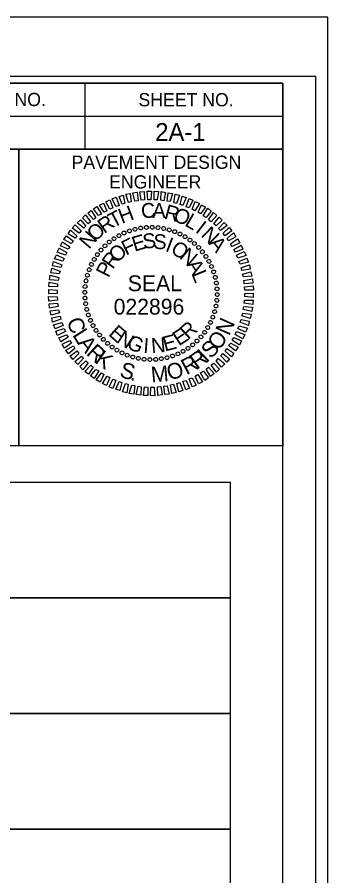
# Model space of a CAD drawing. Extents: x 573732 to 574187, y -53389 to -53257.
# Drawn here: x 573970.18 to 573984.3, y -53296.01 to -53256.95 of the extents above; entities that cross this region are included whole.
import ezdxf

# ---------------------------------------------------------------- set-up
doc = ezdxf.new("R2010")
doc.units = 0
for name, color, linetype in [('Old_Level_19', 7, 'Continuous'), ('Sheet Cutting Line CELL', 7, 'Continuous'), ('Sheet Data Field CELL', 7, 'Continuous'), ('Sheet PE Seal CELL', 7, 'Continuous'), ('Sheet Plot Border Inside CELL', 7, 'Continuous'), ('Sheet Plot Border Outside CELL', 7, 'Continuous'), ('Sheet Typical CELL', 7, 'Continuous')]:
    doc.layers.add(name, color=color, linetype=linetype)

msp = doc.modelspace()

# ---------------------------------------------------------------- linework, layer by layer
at = {"layer": 'Old_Level_19'}
msp.add_lwpolyline([(573928.412, -53278.106), (573979.868, -53278.106), (573979.868, -53283.369), (573928.412, -53283.369)], close=True, dxfattribs=at)
for points in [[(573933.675, -53288.632), (573928.412, -53288.632), (573928.412, -53283.369), (573979.867, -53283.369), (573979.867, -53288.632), (573933.675, -53288.632), (573933.675, -53283.369)], [(573933.675, -53293.895), (573928.412, -53293.895), (573928.412, -53288.631), (573979.867, -53288.631), (573979.867, -53293.895), (573933.675, -53293.895), (573933.675, -53288.631)], [(573933.675, -53299.156), (573928.412, -53299.156), (573928.412, -53293.893), (573979.867, -53293.893), (573979.867, -53299.156), (573933.675, -53299.156), (573933.675, -53293.893)]]:
    msp.add_lwpolyline(points, dxfattribs=at)
at = {"layer": 'Sheet Cutting Line CELL'}
msp.add_line((573984.302, -53256.948), (573782.222, -53256.948), dxfattribs=at)
at = {"layer": 'Sheet PE Seal CELL'}
for p, q in [((573975.04, -53266.763), (573975.04, -53266.763)), ((573975.28, -53266.667), (573975.28, -53266.667)), ((573975.532, -53266.595), (573975.532, -53266.595)), ((573975.796, -53266.547), (573975.796, -53266.547)), ((573976.054, -53266.511), (573976.054, -53266.511)), ((573976.318, -53266.505), (573976.318, -53266.505)), ((573976.582, -53266.523), (573976.582, -53266.523)), ((573976.84, -53266.565), (573976.84, -53266.565)), ((573977.092, -53266.619), (573977.092, -53266.619)), ((573977.344, -53266.703), (573977.344, -53266.703)), ((573977.584, -53266.811), (573977.584, -53266.811)), ((573974.368, -53267.171), (573974.368, -53267.171)), ((573974.578, -53267.021), (573974.578, -53267.021)), ((573974.806, -53266.883), (573974.806, -53266.883)), ((573977.818, -53266.931), (573977.818, -53266.931)), ((573978.034, -53267.081), (573978.034, -53267.081)), ((573973.99, -53267.537), (573973.99, -53267.537)), ((573974.17, -53267.351), (573974.17, -53267.351)), ((573978.244, -53267.243), (573978.244, -53267.243)), ((573978.43, -53267.423), (573978.43, -53267.423)), ((573973.678, -53267.963), (573973.678, -53267.963)), ((573973.828, -53267.747), (573973.828, -53267.747)), ((573978.61, -53267.621), (573978.61, -53267.621)), ((573978.76, -53267.831), (573978.76, -53267.831)), ((573973.558, -53268.197), (573973.558, -53268.197)), ((573978.898, -53268.059), (573978.898, -53268.059)), ((573979.018, -53268.293), (573979.018, -53268.293)), ((573973.366, -53268.689), (573973.366, -53268.689)), ((573973.45, -53268.437), (573973.45, -53268.437)), ((573979.114, -53268.533), (573979.114, -53268.533)), ((573973.312, -53268.941), (573973.312, -53268.941)), ((573979.186, -53268.785), (573979.186, -53268.785)), ((573979.234, -53269.049), (573979.234, -53269.049)), ((573973.252, -53269.463), (573973.252, -53269.463)), ((573973.27, -53269.199), (573973.27, -53269.199)), ((573976.264, -53269.517), (573976.264, -53269.517)), ((573979.27, -53269.307), (573979.27, -53269.307)), ((573973.258, -53269.727), (573973.258, -53269.727)), ((573979.258, -53269.835), (573979.258, -53269.835)), ((573979.276, -53269.571), (573979.276, -53269.571)), ((573973.294, -53269.985), (573973.294, -53269.985)), ((573973.342, -53270.249), (573973.342, -53270.249)), ((573979.216, -53270.093), (573979.216, -53270.093)), ((573973.414, -53270.501), (573973.414, -53270.501)), ((573979.078, -53270.597), (573979.078, -53270.597)), ((573979.162, -53270.345), (573979.162, -53270.345)), ((573973.51, -53270.741), (573973.51, -53270.741)), ((573973.63, -53270.975), (573973.63, -53270.975)), ((573978.85, -53271.071), (573978.85, -53271.071)), ((573978.97, -53270.837), (573978.97, -53270.837)), ((573973.768, -53271.203), (573973.768, -53271.203)), ((573973.918, -53271.413), (573973.918, -53271.413)), ((573978.538, -53271.497), (573978.538, -53271.497)), ((573978.7, -53271.287), (573978.7, -53271.287)), ((573974.098, -53271.611), (573974.098, -53271.611)), ((573974.284, -53271.791), (573974.284, -53271.791)), ((573978.16, -53271.863), (573978.16, -53271.863)), ((573978.358, -53271.683), (573978.358, -53271.683)), ((573974.494, -53271.953), (573974.494, -53271.953)), ((573974.71, -53272.103), (573974.71, -53272.103)), ((573974.944, -53272.223), (573974.944, -53272.223)), ((573977.488, -53272.271), (573977.488, -53272.271)), ((573977.722, -53272.151), (573977.722, -53272.151)), ((573977.95, -53272.013), (573977.95, -53272.013)), ((573975.184, -53272.331), (573975.184, -53272.331)), ((573975.436, -53272.415), (573975.436, -53272.415)), ((573975.688, -53272.469), (573975.688, -53272.469)), ((573975.946, -53272.511), (573975.946, -53272.511)), ((573976.21, -53272.529), (573976.21, -53272.529)), ((573976.474, -53272.523), (573976.474, -53272.523)), ((573976.732, -53272.487), (573976.732, -53272.487)), ((573976.996, -53272.439), (573976.996, -53272.439)), ((573977.248, -53272.367), (573977.248, -53272.367))]:
    msp.add_line(p, q, dxfattribs=at)
for points in [[(573975.82, -53265.281), (573975.754, -53264.897), (573975.958, -53264.873), (573975.964, -53265.263)], [(573976.12, -53265.251), (573976.09, -53264.861), (573976.288, -53264.867), (573976.264, -53265.257)], [(573976.408, -53265.257), (573976.408, -53264.867), (573976.606, -53264.873), (573976.552, -53265.263)], [(573974.398, -53265.683), (573974.206, -53265.347), (573974.392, -53265.263), (573974.53, -53265.629)], [(573974.662, -53265.557), (573974.506, -53265.209), (573974.686, -53265.137), (573974.812, -53265.521)], [(573974.956, -53265.461), (573974.818, -53265.101), (573975.004, -53265.047), (573975.082, -53265.419)], [(573975.244, -53265.383), (573975.118, -53265.005), (573975.322, -53264.963), (573975.37, -53265.353)], [(573975.532, -53265.317), (573975.436, -53264.933), (573975.634, -53264.915), (573975.676, -53265.299)], [(573976.708, -53265.275), (573976.732, -53264.885), (573976.93, -53264.921), (573976.852, -53265.299)], [(573976.996, -53265.323), (573977.05, -53264.939), (573977.248, -53264.969), (573977.14, -53265.341)], [(573977.302, -53265.389), (573977.362, -53264.999), (573977.566, -53265.047), (573977.428, -53265.419)], [(573977.59, -53265.467), (573977.68, -53265.095), (573977.866, -53265.155), (573977.716, -53265.509)], [(573977.86, -53265.575), (573977.998, -53265.197), (573978.166, -53265.269), (573977.998, -53265.617)], [(573973.876, -53265.977), (573973.654, -53265.671), (573973.81, -53265.557), (573974.008, -53265.905)], [(573974.14, -53265.827), (573973.918, -53265.503), (573974.104, -53265.407), (573974.254, -53265.755)], [(573978.13, -53265.689), (573978.28, -53265.335), (573978.466, -53265.419), (573978.262, -53265.755)], [(573978.406, -53265.827), (573978.568, -53265.485), (573978.748, -53265.587), (573978.52, -53265.899)], [(573978.64, -53265.989), (573978.85, -53265.641), (573979.006, -53265.767), (573978.772, -53266.061)], [(573973.408, -53266.343), (573973.144, -53266.079), (573973.288, -53265.935), (573973.522, -53266.259)], [(573973.648, -53266.157), (573973.39, -53265.869), (573973.552, -53265.743), (573973.762, -53266.079)], [(573978.886, -53266.169), (573979.108, -53265.839), (573979.264, -53265.971), (573979, -53266.253)], [(573979.114, -53266.355), (573979.36, -53266.043), (573979.504, -53266.187), (573979.228, -53266.445)], [(573973, -53266.781), (573972.688, -53266.547), (573972.82, -53266.391), (573973.084, -53266.673)], [(573973.21, -53266.553), (573972.904, -53266.307), (573973.054, -53266.169), (573973.306, -53266.457)], [(573979.33, -53266.565), (573979.588, -53266.283), (573979.732, -53266.427), (573979.42, -53266.661)], [(573972.82, -53267.009), (573972.496, -53266.805), (573972.61, -53266.631), (573972.898, -53266.895)], [(573979.54, -53266.781), (573979.816, -53266.511), (573979.942, -53266.673), (573979.624, -53266.901)], [(573979.72, -53267.015), (573980.014, -53266.763), (573980.128, -53266.937), (573979.792, -53267.129)], [(573972.496, -53267.507), (573972.154, -53267.357), (573972.244, -53267.171), (573972.568, -53267.393)], [(573972.64, -53267.249), (573972.304, -53267.069), (573972.424, -53266.901), (573972.736, -53267.141)], [(573979.876, -53267.261), (573980.194, -53267.033), (573980.308, -53267.213), (573979.96, -53267.381)], [(573972.376, -53267.783), (573972.004, -53267.645), (573972.094, -53267.459), (573972.436, -53267.651)], [(573980.032, -53267.525), (573980.368, -53267.315), (573980.446, -53267.501), (573980.104, -53267.639)], [(573980.152, -53267.783), (573980.506, -53267.603), (573980.584, -53267.795), (573980.212, -53267.915)], [(573972.256, -53268.047), (573971.884, -53267.939), (573971.962, -53267.753), (573972.322, -53267.921)], [(573980.26, -53268.065), (573980.626, -53267.909), (573980.692, -53268.095), (573980.32, -53268.191)], [(573972.088, -53268.623), (573971.716, -53268.575), (573971.758, -53268.371), (573972.136, -53268.497)], [(573972.166, -53268.335), (573971.794, -53268.257), (573971.836, -53268.059), (573972.214, -53268.209)], [(573980.356, -53268.353), (573980.74, -53268.215), (573980.776, -53268.413), (573980.398, -53268.479)], [(573972.04, -53268.929), (573971.656, -53268.893), (573971.68, -53268.689), (573972.07, -53268.785)], [(573980.428, -53268.641), (573980.806, -53268.527), (573980.842, -53268.731), (573980.464, -53268.767)], [(573972.01, -53269.217), (573971.62, -53269.205), (573971.632, -53269.007), (573972.022, -53269.073)], [(573980.482, -53268.929), (573980.872, -53268.845), (573980.89, -53269.049), (573980.506, -53269.073)], [(573980.518, -53269.217), (573980.908, -53269.169), (573980.92, -53269.373), (573980.53, -53269.361)], [(573972.004, -53269.517), (573971.614, -53269.535), (573971.614, -53269.331), (573972.004, -53269.373)], [(573980.524, -53269.517), (573980.914, -53269.499), (573980.914, -53269.703), (573980.524, -53269.661)], [(573972.01, -53269.817), (573971.62, -53269.865), (573971.608, -53269.661), (573971.998, -53269.673)], [(573980.518, -53269.817), (573980.908, -53269.829), (573980.896, -53270.027), (573980.506, -53269.961)], [(573972.046, -53270.105), (573971.656, -53270.189), (573971.638, -53269.985), (573972.022, -53269.961)], [(573972.1, -53270.393), (573971.722, -53270.507), (573971.686, -53270.303), (573972.064, -53270.267)], [(573980.488, -53270.105), (573980.872, -53270.141), (573980.848, -53270.345), (573980.458, -53270.249)], [(573972.172, -53270.681), (573971.788, -53270.819), (573971.752, -53270.621), (573972.13, -53270.555)], [(573980.362, -53270.699), (573980.734, -53270.777), (573980.692, -53270.975), (573980.314, -53270.825)], [(573980.44, -53270.411), (573980.812, -53270.459), (573980.77, -53270.663), (573980.392, -53270.537)], [(573972.268, -53270.969), (573971.902, -53271.125), (573971.836, -53270.939), (573972.208, -53270.843)], [(573972.376, -53271.251), (573972.022, -53271.431), (573971.944, -53271.239), (573972.316, -53271.119)], [(573980.272, -53270.987), (573980.644, -53271.095), (573980.566, -53271.281), (573980.206, -53271.113)], [(573972.496, -53271.509), (573972.16, -53271.719), (573972.082, -53271.533), (573972.424, -53271.395)], [(573980.152, -53271.251), (573980.524, -53271.389), (573980.434, -53271.575), (573980.092, -53271.383)], [(573972.652, -53271.773), (573972.334, -53272.001), (573972.22, -53271.821), (573972.568, -53271.653)], [(573972.808, -53272.019), (573972.514, -53272.271), (573972.4, -53272.097), (573972.736, -53271.905)], [(573979.888, -53271.785), (573980.224, -53271.965), (573980.104, -53272.133), (573979.792, -53271.893)], [(573980.032, -53271.527), (573980.374, -53271.677), (573980.284, -53271.863), (573979.96, -53271.641)], [(573972.988, -53272.253), (573972.712, -53272.523), (573972.586, -53272.361), (573972.904, -53272.133)], [(573979.528, -53272.253), (573979.84, -53272.487), (573979.708, -53272.643), (573979.444, -53272.361)], [(573979.708, -53272.025), (573980.032, -53272.229), (573979.918, -53272.403), (573979.63, -53272.139)], [(573973.198, -53272.469), (573972.94, -53272.751), (573972.796, -53272.607), (573973.108, -53272.373)], [(573973.414, -53272.679), (573973.168, -53272.991), (573973.024, -53272.847), (573973.3, -53272.589)], [(573979.318, -53272.481), (573979.624, -53272.727), (573979.474, -53272.865), (573979.222, -53272.577)], [(573973.642, -53272.865), (573973.42, -53273.195), (573973.264, -53273.063), (573973.528, -53272.781)], [(573973.888, -53273.045), (573973.678, -53273.393), (573973.522, -53273.267), (573973.756, -53272.973)], [(573978.652, -53273.057), (573978.874, -53273.363), (573978.718, -53273.477), (573978.52, -53273.129)], [(573978.88, -53272.877), (573979.138, -53273.165), (573978.976, -53273.291), (573978.766, -53272.955)], [(573979.12, -53272.691), (573979.384, -53272.955), (573979.24, -53273.099), (573979.006, -53272.775)], [(573974.122, -53273.207), (573973.96, -53273.549), (573973.78, -53273.447), (573974.008, -53273.135)], [(573974.398, -53273.345), (573974.248, -53273.699), (573974.062, -53273.615), (573974.266, -53273.279)], [(573974.668, -53273.459), (573974.53, -53273.837), (573974.362, -53273.765), (573974.53, -53273.417)], [(573978.13, -53273.351), (573978.322, -53273.687), (573978.136, -53273.771), (573977.998, -53273.405)], [(573978.388, -53273.207), (573978.61, -53273.531), (573978.424, -53273.627), (573978.274, -53273.279)], [(573974.938, -53273.567), (573974.848, -53273.939), (573974.662, -53273.879), (573974.812, -53273.525)], [(573975.226, -53273.645), (573975.166, -53274.035), (573974.962, -53273.987), (573975.1, -53273.615)], [(573975.532, -53273.711), (573975.478, -53274.095), (573975.28, -53274.065), (573975.388, -53273.693)], [(573975.82, -53273.759), (573975.796, -53274.149), (573975.598, -53274.113), (573975.676, -53273.735)], [(573976.12, -53273.777), (573976.12, -53274.167), (573975.922, -53274.161), (573975.976, -53273.771)], [(573976.408, -53273.783), (573976.438, -53274.173), (573976.24, -53274.167), (573976.264, -53273.777)], [(573976.708, -53273.753), (573976.774, -53274.137), (573976.57, -53274.161), (573976.564, -53273.771)], [(573976.996, -53273.717), (573977.092, -53274.101), (573976.894, -53274.119), (573976.852, -53273.735)], [(573977.284, -53273.651), (573977.41, -53274.029), (573977.206, -53274.071), (573977.158, -53273.681)], [(573977.572, -53273.573), (573977.71, -53273.933), (573977.524, -53273.987), (573977.446, -53273.615)], [(573977.866, -53273.477), (573978.022, -53273.825), (573977.842, -53273.897), (573977.716, -53273.513)]]:
    msp.add_lwpolyline(points, close=True, dxfattribs=at)
for centre, major_axis in [((573976.054, -53266.515), (-0.006, 0.0862)), ((573976.316, -53266.508), (0.0015, 0.0864)), ((573976.578, -53266.524), (0.009, 0.0859)), ((573974.805, -53266.885), (-0.0419, 0.0756)), ((573975.04, -53266.767), (-0.0351, 0.0789)), ((573975.284, -53266.671), (-0.0281, 0.0817)), ((573975.536, -53266.597), (-0.0209, 0.0838)), ((573975.793, -53266.544), (-0.0135, 0.0853)), ((573976.838, -53266.562), (0.0165, 0.0848)), ((573977.093, -53266.624), (0.0238, 0.0831)), ((573977.342, -53266.707), (0.031, 0.0807)), ((573977.583, -53266.812), (0.0379, 0.0777)), ((573974.37, -53267.178), (-0.0544, 0.0671)), ((573974.581, -53267.022), (-0.0483, 0.0716)), ((573977.814, -53266.937), (0.0445, 0.0741)), ((573978.033, -53267.082), (0.0508, 0.0699)), ((573978.238, -53267.245), (0.0567, 0.0652)), ((573973.993, -53267.542), (-0.0652, 0.0567)), ((573974.173, -53267.352), (-0.06, 0.0622)), ((573978.429, -53267.426), (0.0622, 0.06)), ((573978.603, -53267.623), (0.0671, 0.0544)), ((573973.684, -53267.967), (-0.0741, 0.0445)), ((573973.829, -53267.748), (-0.0699, 0.0508)), ((573978.759, -53267.834), (0.0716, 0.0483)), ((573978.896, -53268.058), (0.0756, 0.0419)), ((573973.454, -53268.438), (-0.0807, 0.031)), ((573973.559, -53268.197), (-0.0777, 0.0379)), ((573979.013, -53268.293), (0.0789, 0.0351)), ((573973.371, -53268.687), (-0.0831, 0.0238)), ((573979.11, -53268.537), (0.0817, 0.0281)), ((573979.184, -53268.789), (0.0838, 0.0209)), ((573973.271, -53269.202), (-0.0859, 0.009)), ((573973.31, -53268.943), (-0.0848, 0.0165)), ((573979.236, -53269.046), (0.0853, 0.0135)), ((573973.255, -53269.464), (-0.0864, 0.0015)), ((573979.266, -53269.307), (0.0862, 0.006)), ((573979.273, -53269.569), (0.0864, -0.0015)), ((573973.262, -53269.727), (-0.0862, -0.006)), ((573973.291, -53269.988), (-0.0853, -0.0135)), ((573979.257, -53269.831), (0.0859, -0.009)), ((573973.344, -53270.245), (-0.0838, -0.0209)), ((573979.157, -53270.346), (0.0831, -0.0238)), ((573979.218, -53270.091), (0.0848, -0.0165)), ((573973.418, -53270.497), (-0.0817, -0.0281)), ((573973.515, -53270.741), (-0.0789, -0.0351)), ((573979.074, -53270.595), (0.0807, -0.031)), ((573973.632, -53270.976), (-0.0756, -0.0419)), ((573973.769, -53271.2), (-0.0716, -0.0483)), ((573978.844, -53271.067), (0.0741, -0.0445)), ((573978.969, -53270.836), (0.0777, -0.0379)), ((573973.925, -53271.411), (-0.0671, -0.0544)), ((573974.099, -53271.607), (-0.0622, -0.06)), ((573978.535, -53271.491), (0.0652, -0.0567)), ((573978.699, -53271.286), (0.0699, -0.0508)), ((573974.289, -53271.788), (-0.0567, -0.0652)), ((573974.495, -53271.952), (-0.0508, -0.0699)), ((573978.158, -53271.856), (0.0544, -0.0671)), ((573978.355, -53271.682), (0.06, -0.0622)), ((573974.714, -53272.097), (-0.0445, -0.0741)), ((573974.945, -53272.222), (-0.0379, -0.0777)), ((573975.185, -53272.326), (-0.031, -0.0807)), ((573977.244, -53272.362), (0.0281, -0.0817)), ((573977.488, -53272.266), (0.0351, -0.0789)), ((573977.723, -53272.149), (0.0419, -0.0756)), ((573977.947, -53272.012), (0.0483, -0.0716)), ((573975.434, -53272.41), (-0.0238, -0.0831)), ((573975.69, -53272.471), (-0.0165, -0.0848)), ((573975.949, -53272.51), (-0.009, -0.0859)), ((573976.211, -53272.526), (-0.0015, -0.0864)), ((573976.474, -53272.519), (0.006, -0.0862)), ((573976.735, -53272.489), (0.0135, -0.0853)), ((573976.992, -53272.437), (0.0209, -0.0838))]:
    msp.add_ellipse(centre, major_axis=major_axis, ratio=0.999708, dxfattribs=at)
at = {"layer": 'Sheet Plot Border Inside CELL'}
msp.add_lwpolyline([(573983.762, -53259.642), (573783.782, -53259.642), (573783.782, -53386.254), (573983.762, -53386.254)], close=True, dxfattribs=at)
at = {"layer": 'Sheet Plot Border Outside CELL'}
msp.add_lwpolyline([(573984.302, -53256.948), (573782.222, -53256.948), (573782.222, -53388.948), (573984.302, -53388.948)], close=True, dxfattribs=at)
at = {"layer": 'Sheet Typical CELL'}
for p, q in [((573973.262, -53259.954), (573973.262, -53262.954)), ((573958.256, -53261.454), (573982.262, -53261.454)), ((573970.262, -53262.954), (573970.262, -53276.448))]:
    msp.add_line(p, q, dxfattribs=at)
for points in [[(573982.262, -53259.948), (573802.262, -53259.948), (573802.262, -53385.948), (573982.262, -53385.948)], [(573958.256, -53259.948), (573982.262, -53259.948), (573982.262, -53262.954), (573958.256, -53262.954)], [(573958.256, -53262.954), (573970.262, -53262.954), (573970.262, -53276.454), (573958.256, -53276.454)], [(573970.262, -53262.954), (573982.262, -53262.954), (573982.262, -53276.454), (573970.262, -53276.454)]]:
    msp.add_lwpolyline(points, close=True, dxfattribs=at)

# ---------------------------------------------------------------- texts
at = {"layer": 'Sheet Data Field CELL'}
msp.add_text('2A-1', height=0.81, dxfattribs=at).set_placement((573976.458, -53262.576))
at = {"layer": 'Sheet PE Seal CELL'}
for s, height, rotation, p in [('H', 0.677, 20.6195, (573974.938, -53266.355)), ('C', 0.677, 6.2199, (573975.85, -53266.115)), ('A', 0.677, 359.0203, (573976.324, -53266.079)), ('R', 0.677, 344.6211, (573976.828, -53266.103)), ('O', 0.677, 337.4212, (573977.23, -53266.193)), ('R', 0.677, 35.0205, (573974.14, -53266.817)), ('T', 0.677, 27.8198, (573974.548, -53266.553)), ('L', 0.677, 330.2209, (573977.758, -53266.415)), ('O', 0.677, 42.2217, (573973.726, -53267.189)), ('I', 0.677, 323.0201, (573978.244, -53266.703)), ('N', 0.677, 49.4235, (573973.45, -53267.537)), ('E', 0.677, 16.6111, (573975.514, -53267.621)), ('S', 0.677, 7.2556, (573975.928, -53267.495)), ('S', 0.677, 357.9004, (573976.36, -53267.489)), ('N', 0.677, 315.8189, (573978.502, -53266.889)), ('F', 0.677, 25.967, (573975.13, -53267.801)), ('I', 0.677, 339.1896, (573976.876, -53267.573)), ('O', 0.677, 329.8335, (573977.116, -53267.657)), ('A', 0.677, 308.6172, (573978.856, -53267.243)), ('O', 0.677, 44.6812, (573974.734, -53268.155)), ('N', 0.677, 320.4766, (573977.518, -53267.897)), ('R', 0.677, 54.0397, (573974.524, -53268.449)), ('P', 0.677, 63.3989, (573974.332, -53268.833)), ('A', 0.677, 301.7603, (573977.86, -53268.209)), ('SEAL', 0.7198, 360, (573975.208, -53269.415)), ('L', 0.677, 292.4008, (573978.094, -53268.623)), ('C', 0.72, 292.9481, (573972.408, -53270.782)), ('N', 0.72, 65.9082, (573979.818, -53271.476)), ('L', 0.72, 302.5303, (573972.672, -53271.406)), ('E', 0.677, 318.2769, (573974.296, -53271.395)), ('E', 0.677, 33.1241, (573977.53, -53271.929)), ('R', 0.677, 42.4814, (573977.956, -53271.647)), ('N', 0.677, 327.634, (573974.656, -53271.719)), ('G', 0.677, 336.9902, (573975.112, -53271.989)), ('N', 0.677, 5.0564, (573976.3, -53272.235)), ('E', 0.677, 14.4118, (573976.894, -53272.163)), ('O', 0.72, 54.3478, (573979.353, -53272.149)), ('A', 0.72, 308.805, (573972.901, -53271.788)), ('R', 0.72, 317.6453, (573973.289, -53272.277)), ('I', 0.677, 355.7012, (573975.898, -53272.217)), ('S', 0.72, 47.0221, (573978.992, -53272.521)), ('K', 0.72, 325.1256, (573973.674, -53272.641)), ('R', 0.72, 35.7399, (573978.352, -53272.997)), ('I', 0.72, 43.2201, (573978.787, -53272.695)), ('S', 0.72, 343.6099, (573974.798, -53273.301)), ('O', 0.72, 16.6992, (573977.102, -53273.487)), ('R', 0.72, 28.2596, (573977.881, -53273.239)), ('M', 0.72, 5.1697, (573976.292, -53273.575)), ('.', 0.72, 350.9356, (573975.293, -53273.457))]:
    msp.add_text(s, height=height, rotation=rotation, dxfattribs=at).set_placement(p)
msp.add_text('022896', height=0.7198, dxfattribs=at).set_placement((573974.567, -53270.478))
at = {"layer": 'Sheet Typical CELL'}
for s, height, p in [('PROJECT REFERENCE NO.', 0.60001, (573960.92, -53260.992)), ('SHEET NO.', 0.6, (573975.698, -53261.004)), ('PAVEMENT DESIGN', 0.60001, (573972.656, -53263.848)), ('ENGINEER', 0.6, (573974.36, -53264.742))]:
    msp.add_text(s, height=height, dxfattribs=at).set_placement(p)

doc.saveas('drawing.dxf')
